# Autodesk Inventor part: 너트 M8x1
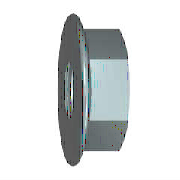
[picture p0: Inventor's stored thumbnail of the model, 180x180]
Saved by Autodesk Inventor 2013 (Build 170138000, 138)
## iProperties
Created: 2015-12
Part Number: 너트 M8x1
Material: 스테인리스강
Description: 플랜지붙이 6각 너트 - 일반 스레드
Document SubType Name: Modeling
Standard: ISO 4161
Designer: mdu
Standard Revision: 2판 1999-03-15
Standards Organization: ISO
Language: ko-KR
Size Designation: M8
Categories: <MemberInstance><Categories><Category DisplayName="조임쇠" InternalName="e4da775c-781d-43d5-af7c-5136215cf5a6" Mnemonic="FSTN"><Category DisplayName="너트" InternalN
Density: 8.08 g/cm^3
Mass: 8.84458 g
Surface Area: 8.9064 cm^2
Volume: 1.09463 cm^3
Author: mdu
IsCustomPart: 1
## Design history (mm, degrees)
sketch "스케치1"
  geometry: L1 (-1.844, 0)-(9.641, 0) reference; L2 (3.107, 6.5)-(2.288, 8.257); L3 (3.107, 6.5)-(8, 6.5); L4 (8, 6.5)-(8, 0); L5 (3.107, 6.5)-(3.107, 0); L6 (0, -1.835)-(0, 11.01) reference; A1 r 1.2 centre (1.2, 7.75) between (2.288, 8.257) and (0, 7.75); 1 further point
  constraints: 8 end point, 3 point on line, 2 perpendicular, 2 point on circle, 2 tangent, 1 centre point, 1 parallel
  dimensions: "d2" = 13 diameter of L3 L1 (= SW); "d4" = 17.9 dimension on A1 L1 (= LADI); "d5" = 1.2 radius of A1 (= PHH); "d15" = 8 distance between parallel lines of L4 L6 (= KOH); "d16" = 25 deg angle of L6 L2 (= KEWI)
revolve "링" sketch "스케치1" stored, may be unused: angle "d8" = 90 deg
sketch "스케치2"
  geometry: L1 (-6.5, -3.753)-(-6.5, 3.753); L2 (-6.5, 3.753)-(0, 7.506); L3 (0, 7.506)-(6.5, 3.753); L4 (6.5, 3.753)-(6.5, -3.753); L5 (6.5, -3.753)-(0, -7.506); L6 (0, -7.506)-(-6.5, -3.753); C1 r 4.9 at (0, 0); C2 r 7.75 at (0, 0) reference; 1 further point
  constraints: 12 end point, 1 centre point, 1 coincident, 1 vertical, 11 other
  dimensions: "d6" = 15.01111 distance of L5.end L2.end (= 1.1547 x SW)
extrude "본체" join sketch "스케치2" distance "d7" = 8 (= KOH); taper "d9" = 0 deg
sketch "스케치3"
  geometry: L1 (2.638, 7.506)-(8, 7.506) reference; L2 (8, 3.753)-(8, 7.506) reference; L3 (0, -7.75)-(0, 7.75) reference; L4 (-1.6, 0)-(9.6, 0) reference; L5 (7.419, 7.506)-(8, 6.5)
  constraints: 2 end point, 2 point on line
  dimensions: "d10" = 30 deg angle of L2 L5 (= ANG1); "d11" = 13 diameter of L5.end L4 (= SW0)
revolve "모따기1" sketch "스케치3" stored, may be unused: angle "d24" = 90 deg
sketch "스케치4"
  geometry: C1 r 7.75 at (0, 0) reference; 1 further point
  constraints: 1 coincident
hole "스레드" sketch "스케치4" at (0, 0) diameter "d25" = 6.917; stored, may be unused: countersink angle "d29" = 82 deg, drill point angle "d31" = 118 deg; dims "d26" = 6, "d27" = 4, "d28" = 2, "d30" = 8
workaxis "Work Axis1"
workplane "Work Plane1"
body "Solid1"
chamfer "모따기2" distance "d12" = 0.67658 (= -0.5 x GD1 + 0.5 x NND); stored, may be unused: angle "d13" = 30 deg, second distance "d46" = 0.67658 (= -0.5 x GD1 + 0.5 x NND)
chamfer "모따기3" distance "d51" = 0.67658 (= -0.5 x GD1 + 0.5 x NND); stored, may be unused: second distance "d52" = 2, angle "d53" = 45 deg
other parameters: "ANG1" = 30 deg [user parameter; used in 1 equation term], "KEWI" = 25 deg [user parameter; used in 1 equation term], "NND" = 8 [user parameter; used in 4 equation terms], "LADI" = 17.9 [user parameter; used in 2 equation terms], "SW" = 13 [user parameter; used in 3 equation terms], "PHH" = 1.2 [user parameter; used in 3 equation terms], "KOH" = 8 (= NND) [user parameter; used in 2 equation terms], "SW0" = 13 [user parameter; used in 1 equation term], "GD1" = 6.64684 (computed from THREADDIA, PTC, TOA) [user parameter; used in 3 equation terms], "d1" = 17.9 (= LADI), "d3" = 1.2 (= PHH), "d45" = 0, "d47" = 0, "d49" = 0, "d54" = 0, "GUL" = 0.67658 (= 0.541266 x PTC) [user parameter], "TPU" = 8 (computed from PTC) [user parameter], "RR" = 1.2 (= PHH) [user parameter], "THREADDIA" = 8 [user parameter; used in 1 equation term], "TOA" = 30 deg [user parameter; used in 1 equation term], "PTC" = 1.25 [user parameter; used in 4 equation terms], "GAL" = 0.67658 (= 0.541266 x PTC) [user parameter], "E0" = 15.015 (= 1.155 x SW) [user parameter]
